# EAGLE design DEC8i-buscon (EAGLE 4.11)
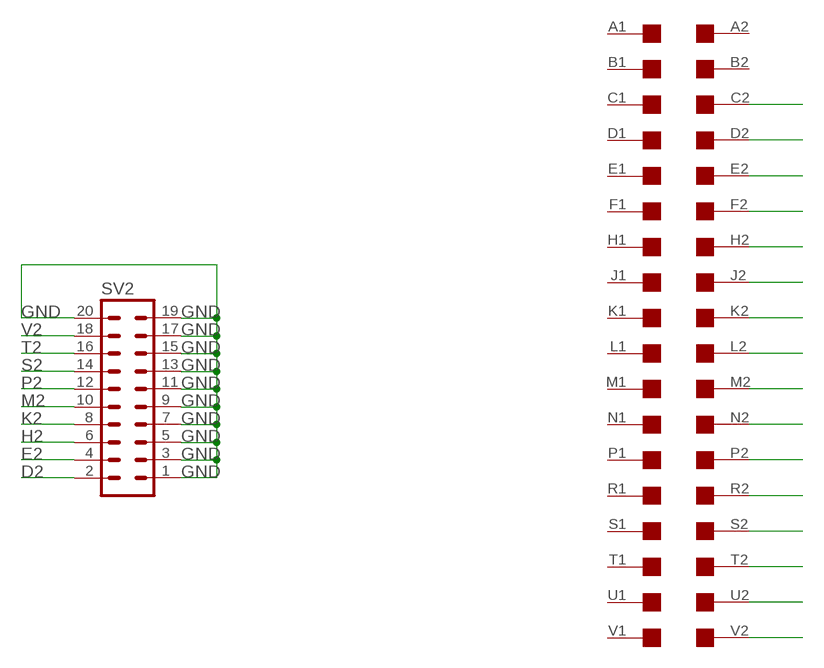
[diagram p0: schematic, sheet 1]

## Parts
SV2  MA10-2  [MA10-2]
U$1  DEC-FLIPCHIP  [DEC-FLIPCHIP]

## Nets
D2: SV2.2 U$1.D2
E2: SV2.4 U$1.E2
GND: SV2.1 SV2.3 SV2.5 SV2.7 SV2.9 SV2.11 SV2.13 SV2.15 SV2.17 SV2.19 SV2.20 U$1.C2 U$1.F2 U$1.J2 U$1.L2 U$1.N2 U$1.R2 U$1.U2
H2: SV2.6 U$1.H2
K2: SV2.8 U$1.K2
M2: SV2.10 U$1.M2
P2: SV2.12 U$1.P2
S2: SV2.14 U$1.S2
T2: SV2.16 U$1.T2
V2: SV2.18 U$1.V2
Unconnected: U$1.A1 U$1.A2 U$1.B1 U$1.B2 U$1.C1 U$1.D1 U$1.E1 U$1.F1 U$1.H1 U$1.J1 U$1.K1 U$1.L1 U$1.M1 U$1.N1 U$1.P1 U$1.R1 U$1.S1 U$1.T1 U$1.U1 U$1.V1

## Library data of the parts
SV2 = con-lstb:MA10-2: PIN HEADER
U$1 = con-dec:DEC-FLIPCHIP: DEC Flip-Chip single card fingers

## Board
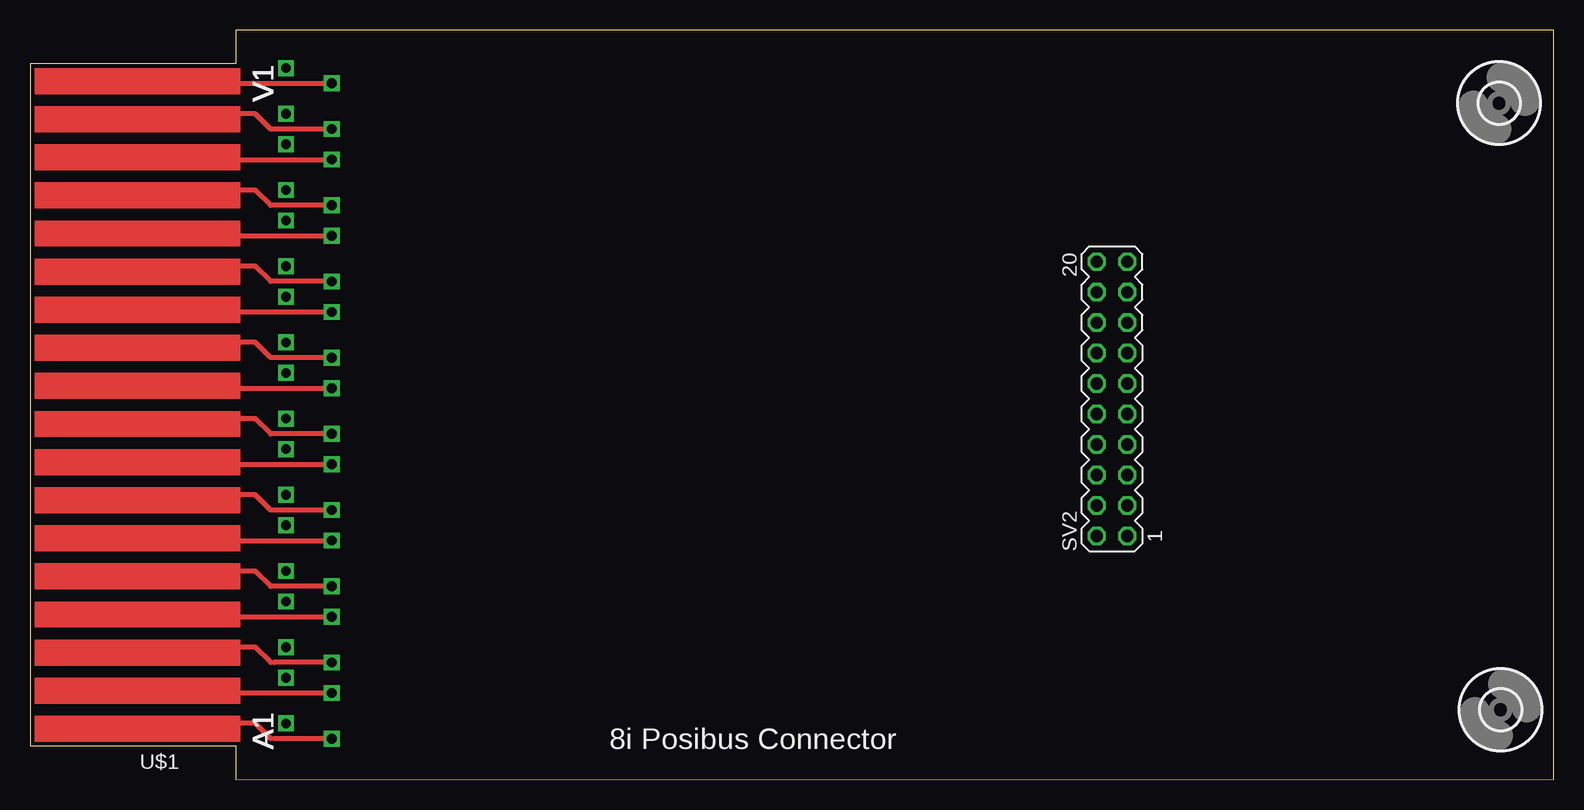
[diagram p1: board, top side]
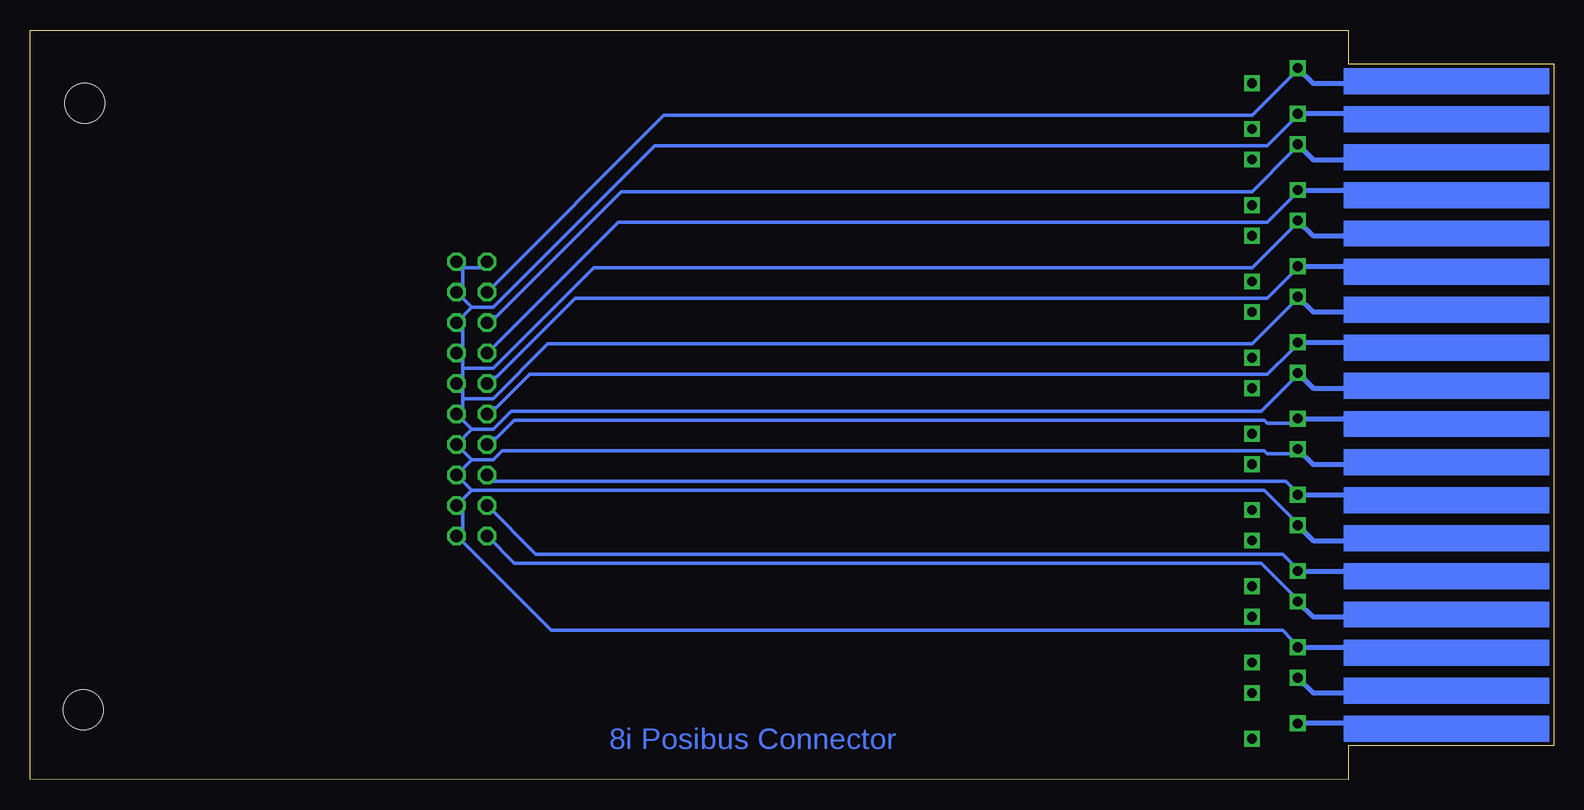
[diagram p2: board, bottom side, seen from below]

Size 126.98 x 62.48 mm. Coordinates in mm from the lower left corner, seen from the top.
Outline: 0,2.83 17.14,2.83 17.14,0 126.98,0.04 126.98,62.45 17.14,62.48 17.14,59.65 0,59.65 0,2.83
Copper layers (1*16): Top 0.035mm / dielectric 1.5mm / Bottom 0.035mm
Design rules "10mils": minimum track width 12mil, minimum drill 28mil, track to track 10mil, track to pad 10mil, pad to pad 10mil, via to via 10mil, smd to smd 10mil, copper to edge 40mil, drill to drill 10mil, minimum pad ring 10mil, minimum via ring 8mil, stop-mask expansion 0mil, vias tented up to drill 0mil, thermal gap 10mil

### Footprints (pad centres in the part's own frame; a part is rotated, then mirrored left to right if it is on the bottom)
MA10-2 = drill 1.016 octagon: 1 -11.43,-1.27; 2 -11.43,1.27; 3 -8.89,-1.27; 4 -8.89,1.27; 5 -6.35,-1.27; 6 -6.35,1.27; 7 -3.81,-1.27; 8 -3.81,1.27; 9 -1.27,-1.27; 10 -1.27,1.27; 11 1.27,-1.27; 12 1.27,1.27; 13 3.81,-1.27; 14 3.81,1.27; 15 6.35,-1.27; 16 6.35,1.27; 17 8.89,-1.27; 18 8.89,1.27; 19 11.43,-1.27; 20 11.43,1.27
DEC-FLIPCHIP = drill 0.813 square: A1 -7.62,27.94; A2 -3.81,26.67; B1 -7.62,24.13; B2 -3.81,22.86; C1 -7.62,21.59; C2 -3.81,20.32; D1 -7.62,17.78; D2 -3.81,16.51; E1 -7.62,15.24; E2 -3.81,13.97; F1 -7.62,11.43; F2 -3.81,10.16; H1 -7.62,8.89; H2 -3.81,7.62; J1 -7.62,5.08; J2 -3.81,3.81; K1 -7.62,2.54; K2 -3.81,1.27; L1 -7.62,-1.27; L2 -3.81,-2.54; M1 -7.62,-3.81; M2 -3.81,-5.08; N1 -7.62,-7.62; N2 -3.81,-8.89; P1 -7.62,-10.16; P2 -3.81,-11.43; R1 -7.62,-13.97; R2 -3.81,-15.24; S1 -7.62,-16.51; S2 -3.81,-17.78; T1 -7.62,-20.32; T2 -3.81,-21.59; U1 -7.62,-22.86; U2 -3.81,-24.13; V1 -7.62,-26.67; V2 -3.81,-27.94
3,3 = hole 3.3: 0,0

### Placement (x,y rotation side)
SV2  90.17,31.75 90 top
U$1  17.52,31.37 180 top
U$2  [3,3]  122.42,56.39 0 top
U$3  [3,3]  122.55,5.84 0 top

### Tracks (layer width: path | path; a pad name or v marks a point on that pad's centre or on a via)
D2
  Bottom 0.305: U$1.D2 21.84,15.49 24.38,18.03 86.61,18.03 SV2.2
E2
  Bottom 0.305: U$1.E2 21.84,18.03 22.6,18.8 84.83,18.8 SV2.4
GND
  Bottom 0.305: 90.93,42.67 89.4,42.67 SV2.20 | 90.17,39.37 88.39,39.37 74.93,52.83 23.87,52.83 21.84,54.86 U$1.U2 | 90.17,39.37 SV2.17 90.93,41.15 90.93,42.67 | 90.17,39.37 SV2.15 90.93,37.59 90.93,36.07 SV2.13 90.93,35.05 90.93,34.29 | 90.93,42.67 SV2.19 | U$1.C2 21.84,11.68 22.6,12.45 83.56,12.45 SV2.1 90.93,20.83 90.93,22.35 SV2.3 90.17,24.13 | 90.17,24.13 24.12,24.13 21.84,21.84 U$1.F2 | 90.17,24.13 SV2.5 90.17,26.67 | 90.17,26.67 88.39,26.67 87.62,27.43 24.12,27.43 23.87,27.18 21.84,27.18 U$1.J2 | 90.17,26.67 SV2.7 90.17,29.21 | 90.17,29.21 88.39,29.21 86.86,30.73 24.38,30.73 21.84,33.27 U$1.L2 | 90.17,29.21 SV2.9 90.93,30.99 90.93,31.75 | 90.93,31.75 90.93,32.51 SV2.11 90.93,33.53 90.93,34.29 | 90.93,31.75 88.39,31.75 83.81,36.32 25.14,36.32 21.84,39.62 U$1.N2 | 90.93,34.29 88.39,34.29 80.01,42.67 25.14,42.67 21.84,45.97 U$1.R2
H2
  Bottom 0.305: U$1.H2 21.84,24.38 22.35,24.89 88.39,24.89 SV2.6
K2
  Bottom 0.305: U$1.K2 21.84,29.72 23.87,29.72 24.12,29.97 86.61,29.97 88.13,28.45 88.39,28.45 SV2.8
M2
  Bottom 0.305: U$1.M2 21.84,35.81 23.87,33.78 85.34,33.78 88.13,30.99 88.39,30.99 SV2.10
P2
  Bottom 0.305: U$1.P2 21.84,42.16 23.87,40.13 81.53,40.13 88.13,33.53 88.39,33.53 SV2.12
S2
  Bottom 0.305: U$1.S2 21.84,48.51 23.87,46.48 77.97,46.48 SV2.14
T2
  Bottom 0.305: U$1.T2 21.84,52.32 25.14,49.02 77.72,49.02 88.13,38.61 88.39,38.61 SV2.16
V2
  Bottom 0.305: U$1.V2 21.84,58.67 25.14,55.37 74.16,55.37 SV2.18

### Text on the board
Bottom: 8i Posibus Connector
tPlace: 8i Posibus Connector
tNames: V1 | V1 | V1 | V1 | V1 | V1 | V1 | V1 | V1 | V1 | V1 | V1 | V1 | V1 | V1 | V1 | V1 | V1 | V1 | V1 | V1 | V1 | V1 | V1 | V1 | V1 | V1 | V1 | V1 | V1 | V1 | V1 | A1 | A1 | A1 | A1 | A1 | A1 | A1 | A1 | A1 | A1 | A1 | A1 | A1 | A1 | A1 | A1 | A1 | A1 | A1 | A1 | A1 | A1 | A1 | A1 | A1 | A1 | A1 | A1 | A1 | A1 | A1 | A1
